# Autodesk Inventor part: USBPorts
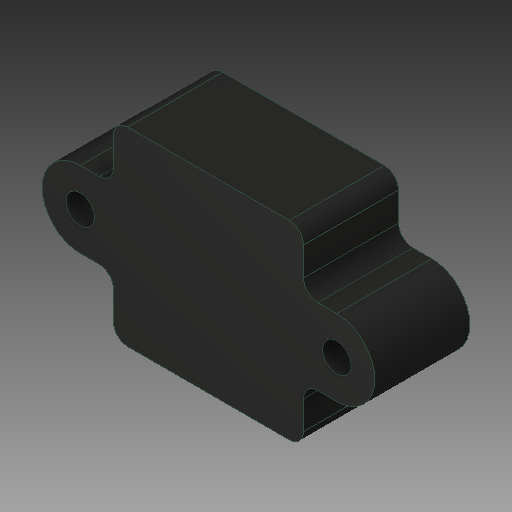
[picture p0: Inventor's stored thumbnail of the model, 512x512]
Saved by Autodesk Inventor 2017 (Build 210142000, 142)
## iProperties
Created: 2017-05
Part Number: USBPorts
Material: Generic
Document SubType Name: Modeling
Designer: Savy
Density: 1 g/cm^3
Appearance: Default
Mass: 4.92128 g
Surface Area: 21.5258 cm^2
Volume: 4.92128 cm^3
Author: Savy
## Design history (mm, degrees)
feature "SOLID1"
body "Solid1"
